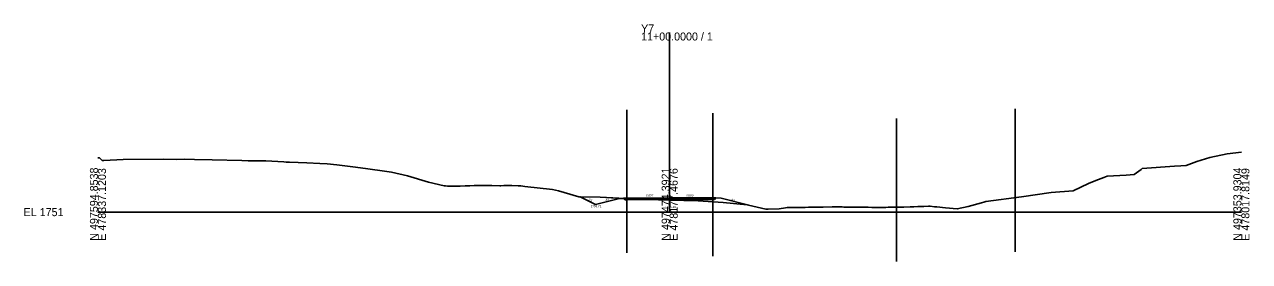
# Model space of a CAD drawing. Extents: x -26 to 403, y -10 to 4071.
# Drawn here: x -25.7 to 402.8, y 982.7 to 1065.7 of the extents above; entities that cross this region are included whole.
import ezdxf

# ---------------------------------------------------------------- set-up
doc = ezdxf.new("R2010")
doc.units = 0
for name, color, linetype in [('Exist Cross Section Cell', 7, 'Continuous'), ('Exist XS Center Line Elevation Label', 7, 'Continuous'), ('Exist XS Ground Line', 7, 'Continuous'), ('Prop Road Sect_ Boring - Header (ID Tx)', 7, 'Continuous'), ('Prop XS Ditch Slope Text', 7, 'Continuous'), ('Prop XS Ditch Standard Text', 7, 'Continuous'), ('Prop XS Dump Level', 7, 'Continuous'), ('Prop XS Earthwork Shape', 7, 'Continuous'), ('Prop XS EOT Tick Mark', 7, 'Continuous'), ('Prop XS Finish Grade', 7, 'Continuous'), ('Prop XS Finish Grade Earthwork', 7, 'Continuous'), ('Prop XS Finish Grade Pavement', 7, 'Continuous'), ('Prop XS Pvmt Edge Slope', 7, 'Continuous'), ('Prop XS SE Text', 7, 'Continuous'), ('Prop XS Side Slope Text', 7, 'Continuous'), ('Prop XS Subgrade Earthwork', 7, 'Continuous'), ('Scratch_Level_2', 7, 'Continuous'), ('Scratch_Level_5', 7, 'Continuous')]:
    doc.layers.add(name, color=color, linetype=linetype)

msp = doc.modelspace()

# ---------------------------------------------------------------- linework, layer by layer
at = {"layer": 'Exist Cross Section Cell'}
for p, q in [((200, 1000), (200, 1062.87)), ((0, 1000), (200, 1000)), ((200, 1000), (400, 1000))]:
    msp.add_line(p, q, dxfattribs=at)
at = {"layer": 'Exist XS Ground Line'}
msp.add_lwpolyline([(0, 1018.95), (0.55, 1018.97), (1.48, 1018.12), (2.05, 1018.05), (8.84, 1018.48), (23.04, 1018.56), (27.47, 1018.48), (30.18, 1018.49), (33.79, 1018.37), (40, 1018.36), (50.39, 1018.07), (52.53, 1018), (58.75, 1017.93), (65.06, 1017.55), (65.89, 1017.52), (67, 1017.46), (73.03, 1017.23), (77.58, 1017.01), (80.17, 1016.88), (83.6, 1016.54), (87.31, 1016.07), (90.11, 1015.72), (94.46, 1015.1), (100.21, 1014.38), (102.64, 1014.02), (108.26, 1012.67), (115.67, 1010.48), (121.17, 1009.23), (121.64, 1009.15), (122.28, 1009.14), (122.63, 1009.13), (124.1, 1009.12), (126.68, 1009.1), (128.46, 1009.17), (130.12, 1009.23), (131.6, 1009.29), (132.31, 1009.29), (134.71, 1009.31), (135.85, 1009.3), (137.02, 1009.3), (137.48, 1009.29), (137.82, 1009.28), (140.59, 1009.26), (140.95, 1009.26), (142.04, 1009.27), (144.07, 1009.3), (144.74, 1009.29), (147.02, 1009.23), (147.89, 1009.18), (149.36, 1009.01), (158.98, 1007.93), (161.1, 1007.4), (163.04, 1006.82), (168.26, 1005.41), (175.67, 1005.19), (188.83, 1004.57), (196.06, 1004.28), (200, 1004.19), (209.93, 1003.99), (218.74, 1003.34), (227.15, 1002.55), (227.61, 1002.49), (233.69, 1001.01), (234.43, 1001.01), (238.31, 1001.14), (240.51, 1001.48), (241.15, 1001.59), (242.72, 1001.62), (243.12, 1001.62), (244.41, 1001.63), (247.43, 1001.68), (248.53, 1001.7), (249.7, 1001.72), (250.61, 1001.73), (251.51, 1001.74), (252.69, 1001.77), (253.73, 1001.79), (256.84, 1001.84), (258.62, 1001.81), (259.97, 1001.8), (260.4, 1001.8), (260.98, 1001.79), (262.19, 1001.78), (263.11, 1001.77), (263.98, 1001.75), (265.13, 1001.73), (266.25, 1001.71), (269.39, 1001.69), (270.77, 1001.67), (271.75, 1001.67), (272.46, 1001.67), (273.44, 1001.67), (274.65, 1001.67), (275.59, 1001.68), (276.44, 1001.7), (277.56, 1001.71), (278.25, 1001.72), (278.78, 1001.72), (281.92, 1001.73), (284.12, 1001.81), (284.91, 1001.84), (285.37, 1001.87), (286.82, 1001.92), (287.38, 1001.93), (288.15, 1001.94), (288.97, 1001.97), (290.56, 1002.05), (291.11, 1002.07), (292.67, 1001.91), (293.09, 1001.88), (293.47, 1001.83), (296.52, 1001.56), (300.61, 1001.14), (304.39, 1001.94), (309.1, 1003.24), (309.85, 1003.44), (310.64, 1003.67), (323.03, 1005.41), (333.48, 1006.83), (341.19, 1007.5), (346.49, 1009.99), (349.14, 1011.03), (351.94, 1012.11), (353.06, 1012.58), (359.68, 1012.97), (362.47, 1013.12), (364.96, 1014.96), (365.35, 1015.24), (376.55, 1016.11), (378.8, 1016.23), (380.74, 1016.3), (384.39, 1017.68), (388.93, 1019.12), (395.03, 1020.43), (400, 1020.96)], dxfattribs=at)
at = {"layer": 'Prop Road Sect_ Boring - Header (ID Tx)'}
for points in [[(185.99, 1004.92), (184.88, 1004.85), (185.4, 1004.33)], [(214.01, 1005.02), (215.12, 1004.96), (214.6, 1004.44)]]:
    msp.add_lwpolyline(points, close=True, dxfattribs=at)
at = {"layer": 'Prop XS Dump Level'}
for p, q in [((185.99, 1004.92), (200, 1005.02)), ((200, 1005.02), (214.01, 1005.02))]:
    msp.add_line(p, q, dxfattribs=at)
at = {"layer": 'Prop XS Earthwork Shape'}
for points in [[(183.56, 1004.82), (182.03, 1004.71), (174.02, 1002.71), (168.64, 1005.4), (175.67, 1005.19)], [(183.97, 1004.8), (183.93, 1004.84), (183.56, 1004.82)], [(183.97, 1004.8), (188.83, 1004.57), (193.19, 1004.39), (185.03, 1004.33), (184.44, 1004.33)], [(218.05, 1004.84), (227.26, 1002.54), (227.15, 1002.55), (218.74, 1003.34), (209.93, 1003.99), (200, 1004.19), (196.06, 1004.28), (193.19, 1004.39), (200, 1004.44), (215.05, 1004.44), (215.63, 1004.44), (216.15, 1004.96)]]:
    msp.add_lwpolyline(points, close=True, dxfattribs=at)
at = {"layer": 'Prop XS EOT Tick Mark'}
for p, q in [((185.03, 1004.91), (185.03, 1005.91)), ((215.05, 1005.02), (215.05, 1006.02))]:
    msp.add_line(p, q, dxfattribs=at)
at = {"layer": 'Prop XS Finish Grade'}
for p, q in [((185.03, 1004.91), (183.93, 1004.84)), ((215.05, 1005.02), (216.15, 1004.96))]:
    msp.add_line(p, q, dxfattribs=at)
at = {"layer": 'Prop XS Finish Grade Earthwork'}
for p, q in [((174.02, 1002.71), (168.64, 1005.4)), ((182.03, 1004.71), (174.02, 1002.71)), ((183.93, 1004.84), (182.03, 1004.71)), ((216.15, 1004.96), (218.05, 1004.84)), ((218.05, 1004.84), (227.23, 1002.54))]:
    msp.add_line(p, q, dxfattribs=at)
at = {"layer": 'Prop XS Finish Grade Pavement'}
for p, q in [((185.03, 1004.91), (200, 1005.02)), ((200, 1005.02), (215.05, 1005.02))]:
    msp.add_line(p, q, dxfattribs=at)
at = {"layer": 'Prop XS Pvmt Edge Slope'}
for p, q in [((185.03, 1004.91), (184.44, 1004.33)), ((215.05, 1005.02), (215.63, 1004.44))]:
    msp.add_line(p, q, dxfattribs=at)
at = {"layer": 'Prop XS Subgrade Earthwork'}
for p, q in [((184.44, 1004.33), (183.93, 1004.84)), ((185.03, 1004.33), (184.44, 1004.33)), ((200, 1004.44), (185.03, 1004.33)), ((215.05, 1004.44), (200, 1004.44)), ((215.05, 1004.44), (215.63, 1004.44)), ((215.63, 1004.44), (216.15, 1004.96))]:
    msp.add_line(p, q, dxfattribs=at)
at = {"layer": 'Scratch_Level_2'}
for p, q in [((185.03, 1035.75), (185.03, 985.75)), ((215.05, 1034.61), (215.05, 984.61)), ((320.85, 1036.11), (320.85, 986.11)), ((279.38, 1032.72), (279.38, 982.72))]:
    msp.add_line(p, q, dxfattribs=at)
at = {"layer": 'Scratch_Level_5'}
msp.add_lwpolyline([(1.48, 1018.12), (2.05, 1018.05), (8.84, 1018.48), (23.04, 1018.56), (27.47, 1018.48), (30.18, 1018.49), (33.79, 1018.37), (40, 1018.36), (50.39, 1018.07), (52.53, 1018), (58.75, 1017.93), (65.06, 1017.55), (65.89, 1017.52), (67, 1017.46), (73.03, 1017.23), (77.58, 1017.01), (80.17, 1016.88), (83.6, 1016.54), (87.31, 1016.07), (90.11, 1015.72), (94.46, 1015.1), (100.21, 1014.38), (102.64, 1014.02), (108.26, 1012.67), (115.67, 1010.48), (121.17, 1009.23), (121.64, 1009.15), (122.28, 1009.14), (122.63, 1009.13), (124.1, 1009.12), (126.68, 1009.1), (128.46, 1009.17), (130.12, 1009.23), (131.6, 1009.29), (132.31, 1009.29), (134.71, 1009.31), (135.85, 1009.3), (137.02, 1009.3), (137.48, 1009.29), (137.82, 1009.28), (140.59, 1009.26), (140.95, 1009.26), (142.04, 1009.27), (144.07, 1009.3), (144.74, 1009.29), (147.02, 1009.23), (147.89, 1009.18), (149.36, 1009.01), (158.98, 1007.93), (161.1, 1007.4), (163.04, 1006.82), (168.26, 1005.41), (175.67, 1005.19), (188.83, 1004.57), (196.06, 1004.28), (200, 1004.19), (209.93, 1003.99), (218.74, 1003.34), (227.15, 1002.55), (227.61, 1002.49), (233.69, 1001.01), (234.43, 1001.01), (238.31, 1001.14), (240.51, 1001.48), (241.15, 1001.59), (242.72, 1001.62), (243.12, 1001.62), (244.41, 1001.63), (247.43, 1001.68), (248.53, 1001.7), (249.7, 1001.72), (250.61, 1001.73), (251.51, 1001.74), (252.69, 1001.77), (253.73, 1001.79), (256.84, 1001.84), (258.62, 1001.81), (259.97, 1001.8), (260.4, 1001.8), (260.98, 1001.79), (262.19, 1001.78), (263.11, 1001.77), (263.98, 1001.75), (265.13, 1001.73), (266.25, 1001.71), (269.39, 1001.69), (270.77, 1001.67), (271.75, 1001.67), (272.46, 1001.67), (273.44, 1001.67), (274.65, 1001.67), (275.59, 1001.68), (276.44, 1001.7), (277.56, 1001.71), (278.25, 1001.72), (278.78, 1001.72), (281.92, 1001.73), (284.12, 1001.81), (284.91, 1001.84), (285.37, 1001.87), (286.82, 1001.92), (287.38, 1001.93), (288.15, 1001.94), (288.97, 1001.97), (290.56, 1002.05), (291.11, 1002.07), (292.67, 1001.91), (293.09, 1001.88), (293.47, 1001.83), (296.52, 1001.56), (300.61, 1001.14), (304.39, 1001.94), (309.1, 1003.24), (309.85, 1003.44), (310.64, 1003.67), (323.03, 1005.41), (333.48, 1006.83), (341.19, 1007.5), (346.49, 1009.99), (349.14, 1011.03), (351.94, 1012.11), (353.06, 1012.58), (359.68, 1012.97), (362.47, 1013.12), (364.96, 1014.96), (365.35, 1015.24), (376.55, 1016.11), (378.8, 1016.23), (380.74, 1016.3), (384.39, 1017.68), (388.93, 1019.12), (395.03, 1020.43), (400, 1020.96)], dxfattribs=at)

# ---------------------------------------------------------------- texts
at = {"layer": 'Exist Cross Section Cell'}
for s, p in [('Y7', (190, 1062.87)), ('11+00.0000 / 1', (190, 1060.07)), ('EL 1751', (-26, 998.6))]:
    msp.add_text(s, height=2.8, dxfattribs=at).set_placement(p)
for s, p in [('N 497594.8538', (0, 990)), ('E 478337.1203', (2.8, 990)), ('N 497474.3921', (200, 990)), ('E 478177.4676', (202.8, 990)), ('N 497353.9304', (400, 990)), ('E 478017.8149', (402.8, 990))]:
    msp.add_text(s, height=2.8, rotation=90, dxfattribs=at).set_placement(p)
at = {"layer": 'Exist XS Center Line Elevation Label'}
msp.add_text('1755.19', height=0.75, dxfattribs=at).set_placement((198.42, 1001.44))
at = {"layer": 'Prop XS Ditch Slope Text'}
msp.add_text('4:1', height=0.75, rotation=14.0255, dxfattribs=at).set_placement((177.66, 1003.75))
at = {"layer": 'Prop XS Ditch Standard Text'}
msp.add_text('1753.71', height=0.75, dxfattribs=at).set_placement((172.35, 1001.71))
at = {"layer": 'Prop XS Dump Level'}
for p in [(182.98, 1004.68), (217.02, 1004.8)]:
    msp.add_text('Case1', height=0.04, dxfattribs=at).set_placement(p)
at = {"layer": 'Prop XS SE Text'}
for s, rotation, p in [('0.007', 0.4147, (191.72, 1005.46)), ('0.000', 360, (205.72, 1005.52))]:
    msp.add_text(s, height=0.75, rotation=rotation, dxfattribs=at).set_placement(p)
at = {"layer": 'Prop XS Side Slope Text'}
for s, rotation, p in [('2:1', 333.4533, (171.52, 1004.22)), ('4:1', 345.9417, (221.48, 1004.09))]:
    msp.add_text(s, height=0.75, rotation=rotation, dxfattribs=at).set_placement(p)

doc.saveas('drawing.dxf')
